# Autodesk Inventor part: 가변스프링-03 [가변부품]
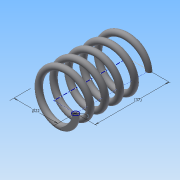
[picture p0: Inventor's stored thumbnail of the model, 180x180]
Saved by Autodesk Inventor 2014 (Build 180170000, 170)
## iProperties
Created: 2015-09
Part Number: 가변스프링-03 [가변부품]
Material: 강철, 탄소
Document SubType Name: Modeling
Designer: study
Density: 7.87 g/cm^3
Appearance: 반연마
Mass: 18.8817 g
Surface Area: 32.5359 cm^2
Volume: 2.3992 cm^3
Author: study
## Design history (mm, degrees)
sketch "스케치1"
  geometry: L1 (0, 0)-(11, 0); L2 (11, 0)-(11, 36.261); L3 (11, 36.261)-(0, 36.261); L4 (0, 36.261)-(0, 0); C1 r 1.5 at (11, 0)
  constraints: 8 end point, 2 parallel, 1 centre point, 1 coincident, 1 horizontal, 1 perpendicular
  dimensions: "d0" = 22 diameter of L2 L4; "d1" = 3 diameter of C1; "d2" = 36.2612 distance between parallel lines of L1 L3 (derived)
feature "코일1" sketch "스케치1" pitch "d3" = 10; turns "d5" = 5; dims "d4" = 36.2612 (= d2), "d6" = 0, angle "d7" = 90 deg, angle "d8" = 90 deg, "d9" = 0, "d10" = 0
node "작업 평면1"
sketch "스케치2"
  geometry: L1 (-12.5, 0)-(-9.5, 0) reference; 1 further point
  constraints: 1 horizontal alignment
extrude "돌출1" cut sketch "스케치2" distance "d12" = 10; taper "d13" = 0 deg
node "작업 평면2"
sketch "스케치3"
  geometry: L1 (-9.5, 0)-(-12.5, 0) reference; 1 further point
  constraints: 1 horizontal alignment
extrude "돌출2" cut sketch "스케치3" distance "d15" = 10; taper "d16" = 0 deg
node "솔리드1"
node "절단 모서리 투영1"
node "절단 모서리 투영2"
other parameters: "d11" = 0, "d14" = 36.2612 (= d2)
